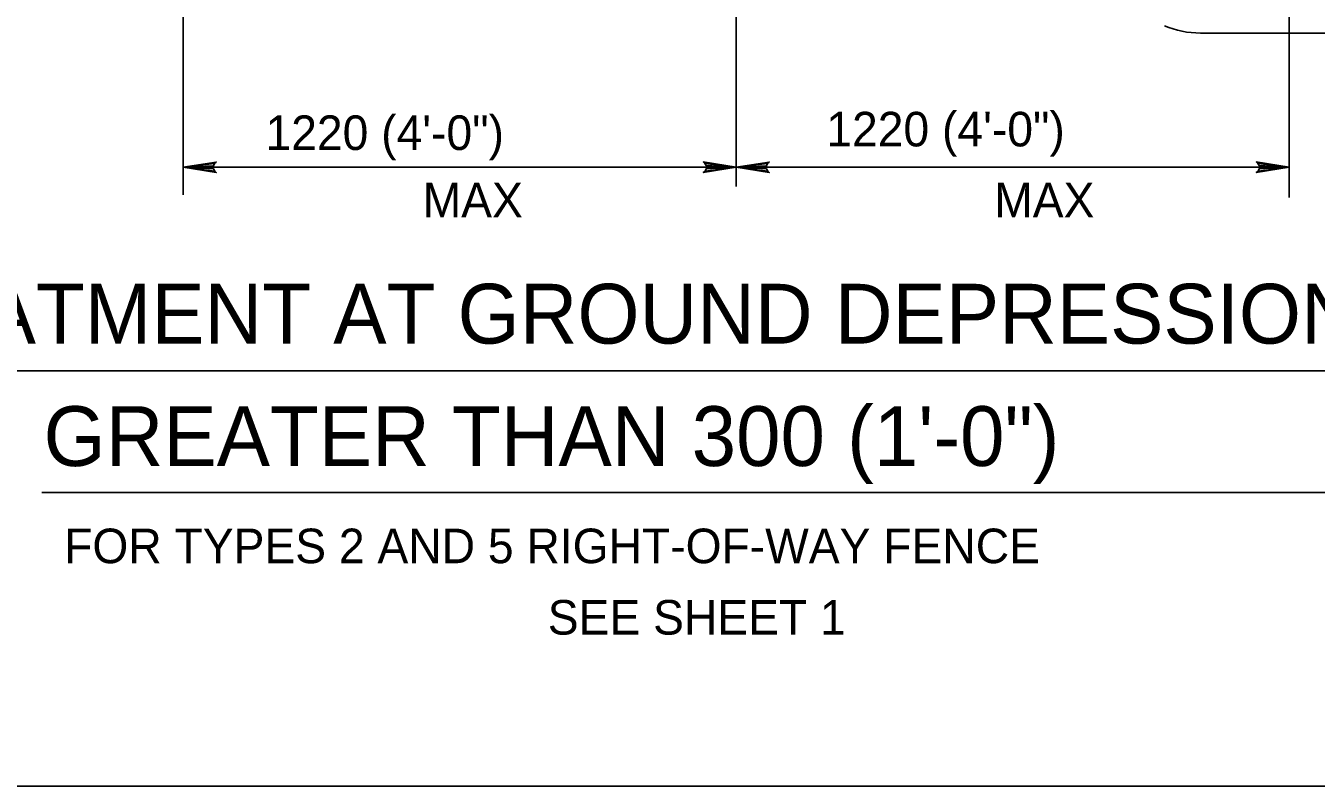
# Model space of a CAD drawing. Extents: x 13 to 918, y -903 to 879.
# Drawn here: x 358.1 to 474.8, y -294.1 to -225.3 of the extents above; entities that cross this region are included whole.
import ezdxf

# ---------------------------------------------------------------- set-up
doc = ezdxf.new("R2010")
doc.units = 0
for name, color, linetype in [('1', 7, 'Continuous'), ('2', 7, 'Continuous'), ('3', 7, 'Continuous')]:
    doc.layers.add(name, color=color, linetype=linetype)

msp = doc.modelspace()

# ---------------------------------------------------------------- linework, layer by layer
at = {"layer": '1'}
msp.add_lwpolyline([(838.2505, -294.06975), (838.2505, 269.93025), (52.2505, 269.93025), (52.2505, -294.06975), (838.2505, -294.06975), (838.2505, -267.71075), (638.2505, -267.71075), (638.2505, -203.03325), (838.2505, -203.03325), (838.2505, -174.06975), (638.2505, -174.06975), (638.2505, -294.06975), (717.052, -294.06975), (717.052, -267.71075), (717.052, -294.06975), (794.052, -294.06975), (794.052, -267.71075), (794.052, -280.02725), (838.2505, -280.02725)], dxfattribs=at)
at = {"layer": '2'}
for p, q in [((372.32525, -112.8975), (372.32525, -240.62675)), ((422.32525, -157.78075), (422.32525, -239.858)), ((472.32525, -157.87675), (472.32525, -240.8745)), ((464.27925, -225.9975), (481.01475, -225.9975)), ((372.32525, -238.133), (422.32525, -238.133)), ((422.32525, -238.133), (472.32525, -238.133))]:
    msp.add_line(p, q, dxfattribs=at)
at = {"layer": '3'}
for p, q in [((337.57525, -256.52675), (506.8315, -256.52675)), ((359.519, -267.51225), (484.1145, -267.51225))]:
    msp.add_line(p, q, dxfattribs=at)
for points in [[(375.16275, -238.48925), (375.0565, -238.283), (372.32525, -238.133), (375.16275, -238.48925), (375.3085, -238.61425), (372.32525, -238.133), (375.05425, -237.9975), (375.15425, -237.7955), (372.32525, -238.133), (375.3085, -237.658), (375.15425, -237.7955)], [(419.48775, -237.77675), (419.594, -237.983), (422.32525, -238.133), (419.48775, -237.77675), (419.34175, -237.65175), (422.32525, -238.133), (419.596, -238.26825), (419.496, -238.4705), (422.32525, -238.133), (419.34175, -238.608), (419.496, -238.4705)], [(425.16275, -238.48925), (425.0565, -238.283), (422.32525, -238.133), (425.16275, -238.48925), (425.3085, -238.61425), (422.32525, -238.133), (425.05425, -237.9975), (425.15425, -237.7955), (422.32525, -238.133), (425.3085, -237.658), (425.15425, -237.7955)], [(469.48775, -237.77675), (469.594, -237.983), (472.32525, -238.133), (469.48775, -237.77675), (469.34175, -237.65175), (472.32525, -238.133), (469.596, -238.26825), (469.496, -238.4705), (472.32525, -238.133), (469.34175, -238.608), (469.496, -238.4705)]]:
    msp.add_lwpolyline(points, dxfattribs=at)
msp.add_arc((464.27922, -217.66496), 8.3325, 247.1874306, 270, dxfattribs=at)

# ---------------------------------------------------------------- texts
for s, height, p in [('1220 (4\'-0")', 3.1249995, (379.75625, -236.568)), ('1220 (4\'-0")', 3.1249995, (430.464, -236.24475)), ('MAX', 3.124999, (393.9675, -242.66175)), ('MAX', 3.124999, (445.64375, -242.66175)), ('TREATMENT AT GROUND DEPRESSIONS', 5.4020865, (339.7315, -254.066)), ('GREATER THAN 300 (1\'-0")', 5.4019995, (359.6895, -265.13075)), ('FOR TYPES 2 AND 5 RIGHT-OF-WAY FENCE', 3.1249995, (361.54825, -273.91625)), ('SEE SHEET 1', 3.1249995, (405.275, -280.37))]:
    msp.add_text(s, height=height, dxfattribs=at).set_placement(p)

doc.saveas('drawing.dxf')
